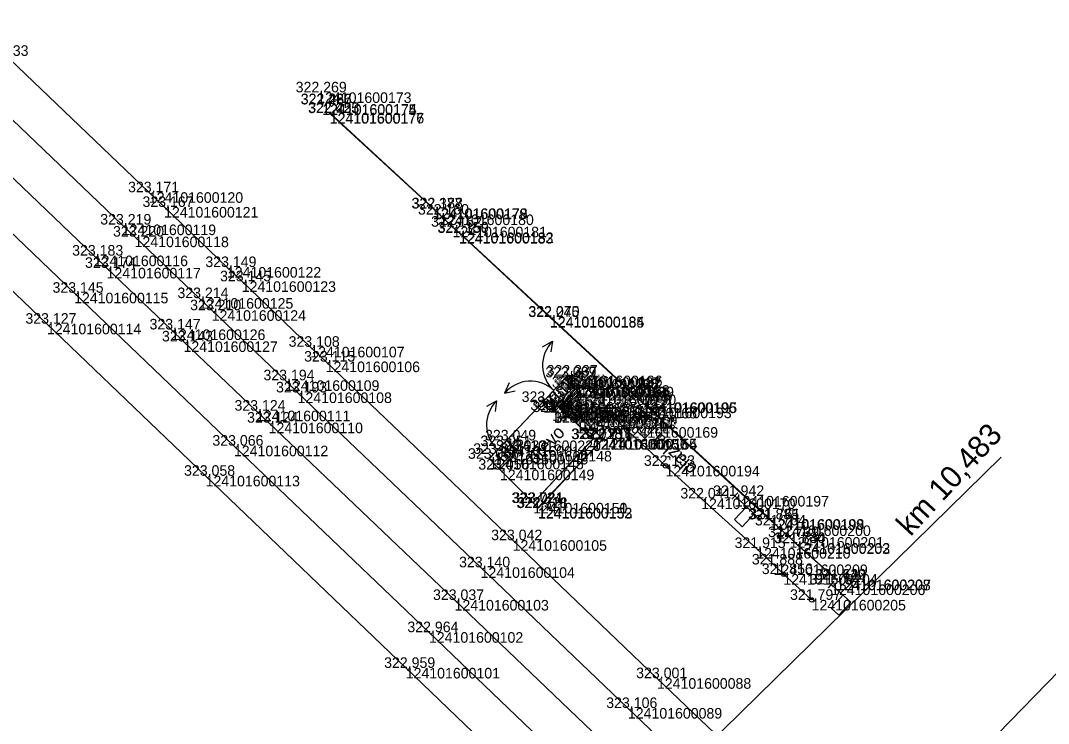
# Model space of a CAD drawing. Extents: x -616949 to -607976, y -1164436 to -1159224.
# Drawn here: x -616343.7 to -616226.9, y -1159650 to -1159570.1 of the extents above; entities that cross this region are included whole.
import ezdxf

# ---------------------------------------------------------------- set-up
doc = ezdxf.new("R2010")
doc.units = 0
for name, color, linetype in [('Vrstva 1', 7, 'Continuous'), ('Vrstva 13', 7, 'Continuous'), ('Vrstva 14', 7, 'Continuous'), ('Vrstva 16', 7, 'Continuous'), ('Vrstva 23', 7, 'Continuous'), ('Vrstva 3', 7, 'Continuous'), ('Vrstva 4', 7, 'Continuous'), ('Vrstva 51', 7, 'Continuous'), ('Vrstva 60', 7, 'Continuous'), ('Vrstva 61', 7, 'Continuous')]:
    doc.layers.add(name, color=color, linetype=linetype)

msp = doc.modelspace()

# ---------------------------------------------------------------- linework, layer by layer
at = {"layer": 'Vrstva 1'}
for points in [[(-616239.15, -1159697.79), (-616239.8, -1159697.28), (-616244.33, -1159693.92), (-616259.78, -1159681.25), (-616268.13, -1159673.95), (-616278.58, -1159664.07), (-616288.41, -1159654.65), (-616299.9, -1159643.65), (-616322.63, -1159621.82), (-616340.65, -1159604.54), (-616363.83, -1159582.4), (-616382.82, -1159564.27), (-616397.71, -1159550.06), (-616401.16, -1159546.79), (-616418.73, -1159530.01), (-616439.27, -1159510.4), (-616452.37, -1159497.82), (-616461.42, -1159488.93), (-616469.22, -1159481.07), (-616478.64, -1159471.37), (-616490.77, -1159457.29), (-616495.92, -1159451.32), (-616496.45, -1159450.7)], [(-616196.14, -1159722.89), (-616196.73, -1159722.32), (-616202.46, -1159716.91), (-616215.79, -1159704.32), (-616232.19, -1159688.78), (-616245.9, -1159675.68), (-616250.85, -1159670.95), (-616252.01, -1159669.85), (-616262.33, -1159660.01), (-616274.66, -1159648.21), (-616291.39, -1159632.22), (-616312.18, -1159612.35), (-616313.6, -1159610.97), (-616321.94, -1159603.01), (-616323.38, -1159601.63), (-616330.7, -1159594.64), (-616332.15, -1159593.27), (-616353.46, -1159572.9), (-616354.89, -1159571.54), (-616372.69, -1159554.54)], [(-616218.05, -1159715.21), (-616218.66, -1159714.63), (-616224.36, -1159709.19), (-616237.66, -1159696.51), (-616252.73, -1159682.15), (-616263.69, -1159671.68), (-616264.9, -1159670.55), (-616281.06, -1159655.11), (-616297.26, -1159639.59), (-616319.41, -1159618.4), (-616337.57, -1159601.02), (-616360.84, -1159578.72), (-616379.28, -1159561.06)], [(-616196.14, -1159722.89), (-616196.73, -1159722.32), (-616202.46, -1159716.91), (-616214.6, -1159702.79), (-616223.47, -1159692.48), (-616229.46, -1159685.74), (-616241.59, -1159673.27), (-616259.02, -1159656.6), (-616271.36, -1159644.82), (-616287.75, -1159629.14), (-616308.99, -1159608.84), (-616310.74, -1159607.16), (-616318.53, -1159599.72), (-616320.21, -1159598.1), (-616327.35, -1159591.27), (-616329.08, -1159589.6), (-616351, -1159568.64)], [(-616166.13, -1159755.81), (-616181.17, -1159743.07), (-616197.09, -1159728.56), (-616212.13, -1159714.43), (-616235.07, -1159692.57), (-616248.23, -1159679.98), (-616265.42, -1159663.57), (-616277.85, -1159651.72), (-616294.35, -1159635.93), (-616315.47, -1159615.78), (-616316.9, -1159614.42), (-616325.14, -1159606.55), (-616326.55, -1159605.19), (-616333.88, -1159598.19), (-616335.34, -1159596.8), (-616356.93, -1159576.13)]]:
    msp.add_lwpolyline(points, dxfattribs=at)
at = {"layer": 'Vrstva 13'}
for p, q in [((-616281.88, -1159610.82), (-616281.59, -1159610.63)), ((-616281.88, -1159610.82), (-616281.88, -1159610.82)), ((-616281.88, -1159610.82), (-616280.85, -1159611.76)), ((-616281.59, -1159610.63), (-616281.59, -1159610.63)), ((-616280.63, -1159611.53), (-616281.59, -1159610.63)), ((-616280.85, -1159611.76), (-616280.63, -1159611.53)), ((-616280.85, -1159611.76), (-616280.85, -1159611.76)), ((-616280.63, -1159611.53), (-616280.63, -1159611.53))]:
    msp.add_line(p, q, dxfattribs=at)
msp.add_lwpolyline([(-616280.85, -1159611.76), (-616280.63, -1159611.53), (-616281.59, -1159610.63)], dxfattribs=at)
at = {"layer": 'Vrstva 14'}
for p, q in [((-616275.13, -1159616.29), (-616270.39, -1159620.69)), ((-616257, -1159632.99), (-616253.79, -1159635.92))]:
    msp.add_line(p, q, dxfattribs=at)
for centre in [(-616275.13, -1159616.29), (-616270.39, -1159620.69), (-616257, -1159632.99), (-616253.79, -1159635.92)]:
    msp.add_circle(centre, 0.25, dxfattribs=at)
at = {"layer": 'Vrstva 16'}
for p, q in [((-616281.88, -1159610.82), (-616284.28, -1159613.43)), ((-616281.88, -1159610.82), (-616280.85, -1159611.76)), ((-616281.44, -1159610.44), (-616280.14, -1159611.71)), ((-616283.29, -1159614.37), (-616280.85, -1159611.76)), ((-616280.85, -1159611.76), (-616280.63, -1159611.97)), ((-616280.63, -1159611.97), (-616280.49, -1159612.08)), ((-616280.49, -1159612.08), (-616280.14, -1159611.71)), ((-616288.44, -1159617.8), (-616284.28, -1159613.43)), ((-616283.06, -1159614.58), (-616284.28, -1159613.43)), ((-616280.03, -1159615.25), (-616280.55, -1159615.8)), ((-616279.93, -1159615.31), (-616280.03, -1159615.25)), ((-616277.49, -1159617.65), (-616279.93, -1159615.31)), ((-616288.44, -1159617.8), (-616287.19, -1159618.99)), ((-616284.88, -1159625.45), (-616277.52, -1159617.62)), ((-616278.59, -1159617.65), (-616277.52, -1159617.62)), ((-616289.19, -1159621.12), (-616287.19, -1159618.99)), ((-616289.19, -1159621.12), (-616290.38, -1159619.89))]:
    msp.add_line(p, q, dxfattribs=at)
for points in [[(-616281.44, -1159610.44), (-616281.59, -1159610.63), (-616280.63, -1159611.53), (-616280.85, -1159611.76)], [(-616280.59, -1159615.8), (-616282.52, -1159614.02), (-616283.06, -1159614.58)], [(-616277.52, -1159617.62), (-616280.03, -1159615.25), (-616280.03, -1159615.25)], [(-616278.66, -1159617.65), (-616280.59, -1159615.8), (-616280.55, -1159615.8), (-616278.59, -1159617.65)], [(-616289.19, -1159621.12), (-616285.43, -1159624.9), (-616285.43, -1159624.91), (-616284.88, -1159625.45), (-616284.86, -1159625.49), (-616277.49, -1159617.65), (-616277.52, -1159617.62)], [(-616285.43, -1159624.91), (-616278.59, -1159617.65), (-616278.66, -1159617.65), (-616285.43, -1159624.9)]]:
    msp.add_lwpolyline(points, dxfattribs=at)
at = {"layer": 'Vrstva 23'}
for p, q in [((-616284.28, -1159613.43), (-616281.88, -1159610.82)), ((-616283.29, -1159614.37), (-616280.85, -1159611.76)), ((-616280.46, -1159612.11), (-616282.16, -1159613.96)), ((-616280.63, -1159611.97), (-616280.85, -1159611.76)), ((-616280.63, -1159611.97), (-616280.63, -1159611.97)), ((-616279.89, -1159612.58), (-616280.63, -1159611.97)), ((-616280.32, -1159612.22), (-616281.87, -1159613.91)), ((-616280.17, -1159612.35), (-616281.55, -1159613.85)), ((-616280.03, -1159612.46), (-616281.26, -1159613.8)), ((-616289.05, -1159618.45), (-616284.28, -1159613.43)), ((-616280.59, -1159615.8), (-616282.52, -1159614.02)), ((-616280.44, -1159615.65), (-616282.16, -1159613.96)), ((-616280.27, -1159615.47), (-616281.87, -1159613.91)), ((-616280.09, -1159615.28), (-616281.55, -1159613.85)), ((-616279.92, -1159615.12), (-616281.26, -1159613.8)), ((-616279.74, -1159614.93), (-616280.59, -1159615.8)), ((-616280.59, -1159615.8), (-616280.59, -1159615.8)), ((-616289.88, -1159619.33), (-616289.05, -1159618.45)), ((-616290.38, -1159619.89), (-616289.88, -1159619.33))]:
    msp.add_line(p, q, dxfattribs=at)
for points in [[(-616284.35, -1159607.15), (-616283.24, -1159606.54), (-616283.4, -1159607.75)], [(-616281.88, -1159610.82), (-616281.59, -1159610.63), (-616281.59, -1159610.63), (-616281.44, -1159610.44)], [(-616288.14, -1159611.27), (-616288.66, -1159612.43), (-616287.47, -1159612.17)], [(-616283.29, -1159614.37), (-616283.06, -1159614.58), (-616282.52, -1159614.02), (-616280.63, -1159611.97)], [(-616280.59, -1159615.8), (-616279.74, -1159614.93), (-616281.01, -1159613.76), (-616279.89, -1159612.58), (-616280.63, -1159611.97), (-616282.52, -1159614.02), (-616281.01, -1159613.76)], [(-616290.68, -1159613.9), (-616289.57, -1159613.3), (-616289.74, -1159614.51)]]:
    msp.add_lwpolyline(points, dxfattribs=at)
for centre, start, end in [((-616280.53, -1159609.26), 134.8865, 228.4064), ((-616285.73, -1159614.9), 46.337, 139.8569), ((-616286.89, -1159616.04), 134.3581, 227.878)]:
    msp.add_arc(centre, 3.83, start, end, dxfattribs=at)
at = {"layer": 'Vrstva 3'}
for p, q in [((-616281.09, -1159667.57), (-616232.24, -1159619.71)), ((-616251.43, -1159670.4), (-616213.9, -1159631.89))]:
    msp.add_line(p, q, dxfattribs=at)
at = {"layer": 'Vrstva 4'}
for p, q in [((-616327.35, -1159591.27), (-616329.08, -1159589.6)), ((-616330.7, -1159594.64), (-616332.15, -1159593.27)), ((-616333.88, -1159598.19), (-616335.34, -1159596.8)), ((-616318.53, -1159599.72), (-616320.21, -1159598.1)), ((-616321.94, -1159603.01), (-616323.38, -1159601.63)), ((-616325.14, -1159606.55), (-616326.55, -1159605.19)), ((-616308.99, -1159608.84), (-616310.74, -1159607.16)), ((-616312.18, -1159612.35), (-616313.6, -1159610.97)), ((-616315.47, -1159615.78), (-616316.9, -1159614.42))]:
    msp.add_line(p, q, dxfattribs=at)
at = {"layer": 'Vrstva 51'}
for p, q in [((-616296.06, -1159592.14), (-616294.57, -1159593.52)), ((-616273.24, -1159613.7), (-616273.91, -1159614.44)), ((-616262.19, -1159623.75), (-616262.87, -1159624.48)), ((-616251.25, -1159633.8), (-616251.92, -1159634.54))]:
    msp.add_line(p, q, dxfattribs=at)
for points in [[(-616308.51, -1159580.57), (-616296.75, -1159591.43), (-616296.06, -1159592.14), (-616296.8, -1159591.46), (-616308.54, -1159580.61)], [(-616294.57, -1159593.52), (-616293.81, -1159594.17), (-616283.51, -1159603.73), (-616272.96, -1159613.48), (-616258.51, -1159626.74), (-616257.78, -1159627.46), (-616258.56, -1159626.78), (-616273.04, -1159613.5), (-616283.51, -1159603.78), (-616293.84, -1159594.23), (-616294.57, -1159593.52)], [(-616253.79, -1159635.92), (-616257, -1159632.99), (-616258.12, -1159631.9), (-616260.08, -1159630.03), (-616266.34, -1159624.4), (-616270.39, -1159620.69), (-616275.13, -1159616.29), (-616277.52, -1159614.1), (-616279.93, -1159615.31)], [(-616273.58, -1159614.07), (-616271.37, -1159616.1), (-616272.72, -1159617.57), (-616273.6, -1159616.76), (-616272.25, -1159615.28)], [(-616262.53, -1159624.11), (-616260.32, -1159626.14), (-616261.67, -1159627.62), (-616262.56, -1159626.8), (-616261.2, -1159625.33)], [(-616257.78, -1159627.46), (-616256.29, -1159628.79), (-616255.58, -1159629.46), (-616250.95, -1159633.61)], [(-616250.98, -1159633.64), (-616255.59, -1159629.5), (-616256.29, -1159628.79)], [(-616251.58, -1159634.17), (-616249.35, -1159636.17), (-616250.69, -1159637.66), (-616251.58, -1159636.86), (-616250.25, -1159635.37)]]:
    msp.add_lwpolyline(points, dxfattribs=at)
at = {"layer": 'Vrstva 60'}
for p, q in [((-616309.95, -1159578.25), (-616309.95, -1159578.25)), ((-616309.38, -1159579.62), (-616309.38, -1159579.62)), ((-616309.37, -1159579.59), (-616309.37, -1159579.59)), ((-616308.54, -1159580.61), (-616308.54, -1159580.61)), ((-616308.51, -1159580.57), (-616308.51, -1159580.57)), ((-616329.08, -1159589.6), (-616329.08, -1159589.6)), ((-616327.35, -1159591.27), (-616327.35, -1159591.27)), ((-616296.8, -1159591.46), (-616296.8, -1159591.46)), ((-616296.75, -1159591.43), (-616296.75, -1159591.43)), ((-616296.06, -1159592.14), (-616296.06, -1159592.14)), ((-616332.15, -1159593.27), (-616332.15, -1159593.27)), ((-616330.7, -1159594.64), (-616330.7, -1159594.64)), ((-616294.57, -1159593.52), (-616294.57, -1159593.52)), ((-616293.84, -1159594.23), (-616293.84, -1159594.23)), ((-616293.81, -1159594.17), (-616293.81, -1159594.17)), ((-616335.34, -1159596.8), (-616335.34, -1159596.8)), ((-616320.21, -1159598.1), (-616320.21, -1159598.1)), ((-616333.88, -1159598.19), (-616333.88, -1159598.19)), ((-616318.53, -1159599.72), (-616318.53, -1159599.72)), ((-616337.57, -1159601.02), (-616337.57, -1159601.02)), ((-616323.38, -1159601.63), (-616323.38, -1159601.63)), ((-616321.94, -1159603.01), (-616321.94, -1159603.01)), ((-616283.51, -1159603.73), (-616283.51, -1159603.73)), ((-616283.51, -1159603.78), (-616283.51, -1159603.78)), ((-616340.65, -1159604.54), (-616340.65, -1159604.54)), ((-616326.55, -1159605.19), (-616326.55, -1159605.19)), ((-616325.14, -1159606.55), (-616325.14, -1159606.55)), ((-616310.74, -1159607.16), (-616310.74, -1159607.16)), ((-616308.99, -1159608.84), (-616308.99, -1159608.84)), ((-616313.6, -1159610.97), (-616313.6, -1159610.97)), ((-616281.88, -1159610.82), (-616281.88, -1159610.82)), ((-616281.88, -1159610.82), (-616281.88, -1159610.82)), ((-616281.59, -1159610.63), (-616281.59, -1159610.63)), ((-616281.59, -1159610.63), (-616281.59, -1159610.63)), ((-616281.59, -1159610.63), (-616281.59, -1159610.63)), ((-616281.44, -1159610.44), (-616281.44, -1159610.44)), ((-616280.85, -1159611.76), (-616280.85, -1159611.76)), ((-616280.85, -1159611.76), (-616280.85, -1159611.76)), ((-616280.85, -1159611.76), (-616280.85, -1159611.76)), ((-616280.63, -1159611.53), (-616280.63, -1159611.53)), ((-616280.63, -1159611.53), (-616280.63, -1159611.53)), ((-616280.63, -1159611.97), (-616280.63, -1159611.97)), ((-616280.63, -1159611.97), (-616280.63, -1159611.97)), ((-616280.49, -1159612.08), (-616280.49, -1159612.08)), ((-616280.14, -1159611.71), (-616280.14, -1159611.71)), ((-616312.18, -1159612.35), (-616312.18, -1159612.35)), ((-616279.89, -1159612.58), (-616279.89, -1159612.58)), ((-616316.9, -1159614.42), (-616316.9, -1159614.42)), ((-616284.28, -1159613.43), (-616284.28, -1159613.43)), ((-616283.29, -1159614.37), (-616283.29, -1159614.37)), ((-616282.52, -1159614.02), (-616282.52, -1159614.02)), ((-616281.01, -1159613.76), (-616281.01, -1159613.76)), ((-616277.52, -1159614.1), (-616277.52, -1159614.1)), ((-616273.58, -1159614.07), (-616273.58, -1159614.07)), ((-616273.04, -1159613.5), (-616273.04, -1159613.5)), ((-616272.96, -1159613.48), (-616272.96, -1159613.48)), ((-616283.06, -1159614.58), (-616283.06, -1159614.58)), ((-616280.03, -1159615.25), (-616280.03, -1159615.25)), ((-616280.03, -1159615.25), (-616280.03, -1159615.25)), ((-616279.93, -1159615.31), (-616279.93, -1159615.31)), ((-616279.74, -1159614.93), (-616279.74, -1159614.93)), ((-616315.47, -1159615.78), (-616315.47, -1159615.78)), ((-616280.59, -1159615.8), (-616280.59, -1159615.8)), ((-616280.59, -1159615.8), (-616280.59, -1159615.8)), ((-616280.55, -1159615.8), (-616280.55, -1159615.8)), ((-616275.13, -1159616.29), (-616275.13, -1159616.29)), ((-616288.44, -1159617.8), (-616288.44, -1159617.8)), ((-616278.66, -1159617.65), (-616278.66, -1159617.65)), ((-616278.59, -1159617.65), (-616278.59, -1159617.65)), ((-616277.52, -1159617.62), (-616277.52, -1159617.62)), ((-616277.49, -1159617.65), (-616277.49, -1159617.65)), ((-616319.41, -1159618.4), (-616319.41, -1159618.4)), ((-616289.05, -1159618.45), (-616289.05, -1159618.45)), ((-616287.19, -1159618.99), (-616287.19, -1159618.99)), ((-616290.38, -1159619.89), (-616290.38, -1159619.89)), ((-616289.88, -1159619.33), (-616289.88, -1159619.33)), ((-616289.19, -1159621.12), (-616289.19, -1159621.12)), ((-616270.39, -1159620.69), (-616270.39, -1159620.69)), ((-616322.63, -1159621.82), (-616322.63, -1159621.82)), ((-616285.43, -1159624.9), (-616285.43, -1159624.9)), ((-616285.43, -1159624.91), (-616285.43, -1159624.91)), ((-616266.34, -1159624.4), (-616266.34, -1159624.4)), ((-616262.53, -1159624.11), (-616262.53, -1159624.11)), ((-616284.88, -1159625.45), (-616284.88, -1159625.45)), ((-616284.86, -1159625.49), (-616284.86, -1159625.49)), ((-616258.56, -1159626.78), (-616258.56, -1159626.78)), ((-616258.51, -1159626.74), (-616258.51, -1159626.74)), ((-616257.78, -1159627.46), (-616257.78, -1159627.46)), ((-616287.75, -1159629.14), (-616287.75, -1159629.14)), ((-616256.29, -1159628.79), (-616256.29, -1159628.79)), ((-616255.59, -1159629.5), (-616255.59, -1159629.5)), ((-616255.58, -1159629.46), (-616255.58, -1159629.46)), ((-616260.08, -1159630.03), (-616260.08, -1159630.03)), ((-616258.12, -1159631.9), (-616258.12, -1159631.9)), ((-616291.39, -1159632.22), (-616291.39, -1159632.22)), ((-616257, -1159632.99), (-616257, -1159632.99)), ((-616251.58, -1159634.17), (-616251.58, -1159634.17)), ((-616250.98, -1159633.64), (-616250.98, -1159633.64)), ((-616250.95, -1159633.61), (-616250.95, -1159633.61)), ((-616294.35, -1159635.93), (-616294.35, -1159635.93)), ((-616253.79, -1159635.92), (-616253.79, -1159635.92)), ((-616297.26, -1159639.59), (-616297.26, -1159639.59)), ((-616299.9, -1159643.65), (-616299.9, -1159643.65)), ((-616271.36, -1159644.82), (-616271.36, -1159644.82)), ((-616274.66, -1159648.21), (-616274.66, -1159648.21))]:
    msp.add_line(p, q, dxfattribs=at)

# ---------------------------------------------------------------- texts
at = {"layer": 'Vrstva 16'}
for s, rotation, p in [('guma', 46.8585, (-616283.66, -1159614.58)), ('dřevo', 46.9617, (-616285.14, -1159620.65)), ('dl.', 46.7315, (-616288.77, -1159620.41))]:
    msp.add_text(s, height=1.5, rotation=rotation, dxfattribs=at).set_placement(p)
at = {"layer": 'Vrstva 3'}
msp.add_text('km 10,483', height=2.5, rotation=47.4118, dxfattribs=at).set_placement((-616242.56, -1159628.79))
at = {"layer": 'Vrstva 51'}
msp.add_text('dlažba', height=1.5, rotation=137.5024, dxfattribs=at).set_placement((-616266.7, -1159620.82))
at = {"layer": 'Vrstva 60'}
for s, p in [('124101600133', (-616353.46, -1159574.1)), ('124101600173', (-616309.95, -1159579.45)), ('124101600175', (-616309.38, -1159580.82)), ('124101600174', (-616309.37, -1159580.79)), ('124101600177', (-616308.54, -1159581.81)), ('124101600176', (-616308.51, -1159581.77)), ('124101600120', (-616329.08, -1159590.8)), ('124101600121', (-616327.35, -1159592.47)), ('124101600179', (-616296.8, -1159592.66)), ('124101600178', (-616296.75, -1159592.63)), ('124101600180', (-616296.06, -1159593.33)), ('124101600119', (-616332.15, -1159594.47)), ('124101600118', (-616330.7, -1159595.84)), ('124101600181', (-616294.57, -1159594.72)), ('124101600183', (-616293.84, -1159595.43)), ('124101600182', (-616293.81, -1159595.37)), ('124101600116', (-616335.34, -1159598)), ('124101600122', (-616320.21, -1159599.3)), ('124101600117', (-616333.88, -1159599.39)), ('124101600123', (-616318.53, -1159600.92)), ('124101600115', (-616337.57, -1159602.22)), ('124101600125', (-616323.38, -1159602.83)), ('124101600124', (-616321.94, -1159604.21)), ('124101600185', (-616283.51, -1159604.98)), ('124101600184', (-616283.51, -1159604.93)), ('124101600114', (-616340.65, -1159605.74)), ('124101600126', (-616326.55, -1159606.39)), ('124101600127', (-616325.14, -1159607.75)), ('124101600107', (-616310.74, -1159608.36)), ('124101600106', (-616308.99, -1159610.04)), ('124101600109', (-616313.6, -1159612.17)), ('124101600166', (-616281.88, -1159612.02)), ('124101600225', (-616281.88, -1159612.02)), ('124101600187', (-616281.59, -1159611.83)), ('124101600221', (-616281.59, -1159611.83)), ('124101600222', (-616281.59, -1159611.83)), ('124101600186', (-616281.44, -1159611.64)), ('124101600167', (-616280.85, -1159612.96)), ('124101600224', (-616280.85, -1159612.96)), ('124101600227', (-616280.85, -1159612.96)), ('124101600188', (-616280.63, -1159612.73)), ('124101600223', (-616280.63, -1159612.73)), ('124101600191', (-616280.63, -1159613.17)), ('124101600228', (-616280.63, -1159613.17)), ('124101600226', (-616280.49, -1159613.28)), ('124101600189', (-616280.14, -1159612.91)), ('124101600108', (-616312.18, -1159613.55)), ('124101600190', (-616279.89, -1159613.78)), ('124101600111', (-616316.9, -1159615.62)), ('124101600165', (-616284.28, -1159614.63)), ('124101600230', (-616283.29, -1159615.57)), ('124101600163', (-616282.52, -1159615.22)), ('124101600192', (-616281.01, -1159614.96)), ('124101600168', (-616277.52, -1159615.3)), ('124101600193', (-616273.58, -1159615.27)), ('124101600196', (-616273.04, -1159614.7)), ('124101600195', (-616272.96, -1159614.68)), ('124101600164', (-616283.06, -1159615.78)), ('124101600161', (-616280.03, -1159616.45)), ('124101600217', (-616280.03, -1159616.45)), ('124101600160', (-616279.93, -1159616.51)), ('124101600159', (-616279.74, -1159616.13)), ('124101600110', (-616315.47, -1159616.98)), ('124101600158', (-616280.59, -1159617)), ('124101600229', (-616280.59, -1159617)), ('124101600162', (-616280.55, -1159617)), ('124101600169', (-616275.13, -1159617.49)), ('124101600220', (-616288.44, -1159619.01)), ('124101600157', (-616278.66, -1159618.85)), ('124101600156', (-616278.59, -1159618.85)), ('124101600155', (-616277.52, -1159618.82)), ('124101600154', (-616277.49, -1159618.84)), ('124101600112', (-616319.41, -1159619.6)), ('124101600147', (-616289.05, -1159619.65)), ('124101600148', (-616287.19, -1159620.19)), ('124101600145', (-616290.38, -1159621.08)), ('124101600146', (-616289.88, -1159620.53)), ('124101600149', (-616289.19, -1159622.32)), ('124101600194', (-616270.39, -1159621.89)), ('124101600113', (-616322.63, -1159623.02)), ('124101600150', (-616285.43, -1159626.1)), ('124101600151', (-616285.43, -1159626.1)), ('124101600170', (-616266.34, -1159625.6)), ('124101600197', (-616262.53, -1159625.31)), ('124101600152', (-616284.88, -1159626.65)), ('124101600153', (-616284.86, -1159626.69)), ('124101600199', (-616258.56, -1159627.98)), ('124101600198', (-616258.51, -1159627.94)), ('124101600200', (-616257.78, -1159628.66)), ('124101600105', (-616287.75, -1159630.34)), ('124101600201', (-616256.29, -1159629.99)), ('124101600203', (-616255.59, -1159630.7)), ('124101600202', (-616255.58, -1159630.66)), ('124101600210', (-616260.08, -1159631.23)), ('124101600209', (-616258.12, -1159633.1)), ('124101600104', (-616291.39, -1159633.42)), ('124101600204', (-616257, -1159634.19)), ('124101600206', (-616251.58, -1159635.37)), ('124101600208', (-616250.98, -1159634.84)), ('124101600207', (-616250.95, -1159634.81)), ('124101600103', (-616294.35, -1159637.13)), ('124101600205', (-616253.79, -1159637.12)), ('124101600102', (-616297.26, -1159640.79)), ('124101600101', (-616299.9, -1159644.85)), ('124101600088', (-616271.36, -1159646.02)), ('124101600089', (-616274.66, -1159649.41))]:
    msp.add_text(s, height=1.2, dxfattribs=at).set_placement(p)
at = {"layer": 'Vrstva 61'}
for s, p in [('322.269', (-616312.4, -1159578.25)), ('322.436', (-616311.83, -1159579.62)), ('322.267', (-616311.82, -1159579.59)), ('322.425', (-616311, -1159580.61)), ('322.253', (-616310.96, -1159580.57)), ('323.171', (-616331.44, -1159589.6)), ('323.167', (-616329.8, -1159591.27)), ('322.377', (-616299.25, -1159591.46)), ('322.188', (-616299.21, -1159591.43)), ('322.160', (-616298.51, -1159592.14)), ('323.219', (-616334.6, -1159593.27)), ('322.152', (-616297.02, -1159593.52)), ('323.220', (-616333.15, -1159594.64)), ('322.350', (-616296.29, -1159594.23)), ('322.159', (-616296.26, -1159594.17)), ('323.183', (-616337.79, -1159596.8)), ('323.174', (-616336.33, -1159598.19)), ('323.149', (-616322.66, -1159598.1)), ('323.145', (-616320.99, -1159599.72)), ('323.145', (-616340.02, -1159601.02)), ('323.214', (-616325.83, -1159601.63)), ('323.210', (-616324.39, -1159603.01)), ('322.245', (-616285.97, -1159603.78)), ('322.070', (-616285.96, -1159603.73)), ('323.127', (-616343.1, -1159604.54)), ('323.147', (-616329, -1159605.19)), ('323.143', (-616327.59, -1159606.55)), ('323.108', (-616313.2, -1159607.16)), ('323.115', (-616311.44, -1159608.84)), ('323.194', (-616316.06, -1159610.97)), ('323.067', (-616284.33, -1159610.82)), ('323.267', (-616284.33, -1159610.82)), ('322.389', (-616284.04, -1159610.63)), ('323.267', (-616284.04, -1159610.63)), ('323.067', (-616284.04, -1159610.63)), ('322.337', (-616283.89, -1159610.44)), ('323.047', (-616283.3, -1159611.76)), ('323.247', (-616283.3, -1159611.76)), ('322.363', (-616283.3, -1159611.76)), ('322.363', (-616283.08, -1159611.53)), ('323.247', (-616283.08, -1159611.53)), ('323.045', (-616283.08, -1159611.97)), ('322.401', (-616282.98, -1159611.97)), ('322.401', (-616282.85, -1159612.08)), ('322.306', (-616282.59, -1159611.71)), ('323.193', (-616314.63, -1159612.35)), ('322.401', (-616282.25, -1159612.58)), ('323.124', (-616319.35, -1159614.42)), ('323.032', (-616286.73, -1159613.43)), ('323.043', (-616285.74, -1159614.37)), ('323.034', (-616284.97, -1159614.02)), ('322.446', (-616283.46, -1159613.76)), ('322.271', (-616279.87, -1159614.1)), ('322.111', (-616275.93, -1159614.07)), ('322.132', (-616275.48, -1159613.5)), ('321.949', (-616275.41, -1159613.48)), ('323.045', (-616285.51, -1159614.58)), ('322.725', (-616282.49, -1159615.25)), ('322.365', (-616282.49, -1159615.25)), ('322.365', (-616282.39, -1159615.31)), ('322.372', (-616282.19, -1159614.93)), ('323.124', (-616317.92, -1159615.78)), ('323.025', (-616283.05, -1159615.8)), ('322.372', (-616283.04, -1159615.8)), ('322.727', (-616283, -1159615.8)), ('322.218', (-616277.58, -1159616.29)), ('323.049', (-616290.89, -1159617.8)), ('323.018', (-616281.11, -1159617.65)), ('322.725', (-616281.04, -1159617.65)), ('322.216', (-616279.95, -1159617.65)), ('322.711', (-616279.87, -1159617.62)), ('323.066', (-616321.86, -1159618.4)), ('323.051', (-616291.41, -1159618.45)), ('323.033', (-616289.64, -1159618.99)), ('323.066', (-616292.83, -1159619.89)), ('323.051', (-616292.23, -1159619.33)), ('323.056', (-616291.65, -1159621.12)), ('322.133', (-616272.84, -1159620.69)), ('323.058', (-616325.08, -1159621.82)), ('322.724', (-616287.88, -1159624.91)), ('323.021', (-616287.79, -1159624.9)), ('322.041', (-616268.7, -1159624.4)), ('321.942', (-616264.98, -1159624.11)), ('322.318', (-616287.32, -1159625.49)), ('322.721', (-616287.24, -1159625.45)), ('321.885', (-616261.01, -1159626.78)), ('321.761', (-616260.87, -1159626.74)), ('321.764', (-616260.23, -1159627.46)), ('323.042', (-616290.19, -1159629.14)), ('321.739', (-616258.74, -1159628.79)), ('321.844', (-616258.04, -1159629.5)), ('321.730', (-616258.03, -1159629.46)), ('321.915', (-616262.54, -1159630.03)), ('321.888', (-616260.58, -1159631.9)), ('323.140', (-616293.84, -1159632.22)), ('321.856', (-616259.45, -1159632.99)), ('321.754', (-616254.04, -1159634.17)), ('321.742', (-616253.43, -1159633.64)), ('321.620', (-616253.4, -1159633.61)), ('323.037', (-616296.8, -1159635.93)), ('321.797', (-616256.24, -1159635.92)), ('322.964', (-616299.71, -1159639.59)), ('322.959', (-616302.35, -1159643.65)), ('323.001', (-616273.72, -1159644.82)), ('323.106', (-616277.12, -1159648.21))]:
    msp.add_text(s, height=1.2, dxfattribs=at).set_placement(p)

doc.saveas('drawing.dxf')
